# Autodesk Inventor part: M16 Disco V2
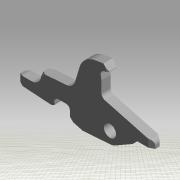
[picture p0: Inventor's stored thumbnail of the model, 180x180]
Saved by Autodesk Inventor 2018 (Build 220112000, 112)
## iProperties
Created: 2019-01
Part Number: M16 Disco V2
Material: Generic
Document SubType Name: Modeling
Designer: johne
Appearance: Default
Author: johne
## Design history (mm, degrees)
feature "Solid1"
fillet "Fillet2" dims "d4" = 0.127
body "Solid2"
